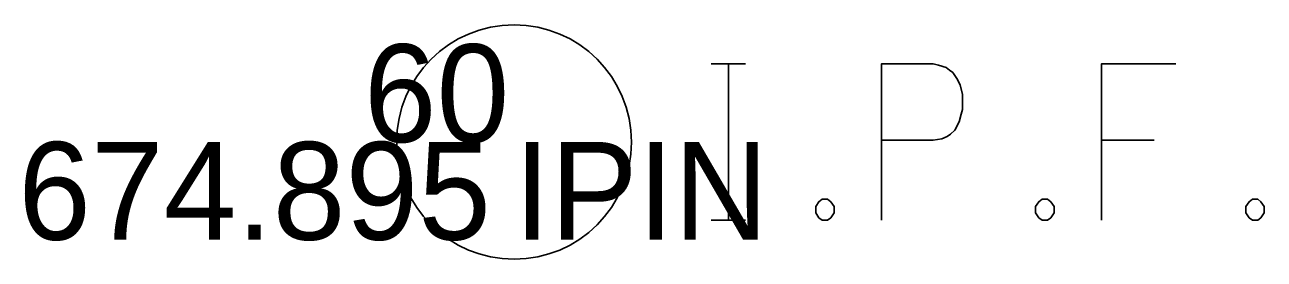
# Model space of a CAD drawing. Extents: x 2197382 to 2204062, y 634117 to 636522.
# Drawn here: x 2198210.64 to 2198223.31, y 636315.52 to 636317.92 of the extents above; entities that cross this region are included whole.
import ezdxf

# ---------------------------------------------------------------- set-up
doc = ezdxf.new("R2010")
doc.units = 0
for name, color, linetype in [('SH_Border', 7, 'Continuous'), ('SH_Cut_Line', 7, 'Continuous'), ('SH_Data', 7, 'Continuous'), ('SV_X_Mon_Cells_Found', 7, 'Continuous')]:
    doc.layers.add(name, color=color, linetype=linetype)

msp = doc.modelspace()

# ---------------------------------------------------------------- linework, layer by layer
at = {"layer": 'SV_X_Mon_Cells_Found'}
for points in [[(2198217.654, 636317.52), (2198218.007, 636317.52)], [(2198217.831, 636315.92), (2198217.831, 636317.52)], [(2198219.396, 636315.92), (2198219.396, 636317.52), (2198219.925, 636317.52), (2198219.98, 636317.508), (2198220.057, 636317.482), (2198220.091, 636317.457), (2198220.124, 636317.432), (2198220.168, 636317.369), (2198220.201, 636317.306), (2198220.223, 636317.205), (2198220.223, 636317.054), (2198220.212, 636317.004), (2198220.19, 636316.928), (2198220.146, 636316.84), (2198220.101, 636316.802), (2198220.068, 636316.777), (2198220.013, 636316.752), (2198219.925, 636316.739), (2198219.396, 636316.739)], [(2198222.405, 636317.52), (2198221.645, 636317.52), (2198221.645, 636315.92)], [(2198221.645, 636316.739), (2198222.185, 636316.739)], [(2198218.79, 636316.135), (2198218.845, 636316.135), (2198218.878, 636316.109), (2198218.911, 636316.059), (2198218.911, 636315.996), (2198218.878, 636315.945), (2198218.845, 636315.92), (2198218.79, 636315.92), (2198218.757, 636315.945), (2198218.724, 636315.996), (2198218.724, 636316.059), (2198218.757, 636316.109), (2198218.79, 636316.135)], [(2198221.039, 636316.135), (2198221.094, 636316.135), (2198221.127, 636316.109), (2198221.16, 636316.059), (2198221.16, 636315.996), (2198221.127, 636315.945), (2198221.094, 636315.92), (2198221.039, 636315.92), (2198221.005, 636315.945), (2198220.972, 636315.996), (2198220.972, 636316.059), (2198221.005, 636316.109), (2198221.039, 636316.135)], [(2198223.188, 636316.135), (2198223.243, 636316.135), (2198223.276, 636316.109), (2198223.309, 636316.059), (2198223.309, 636315.996), (2198223.276, 636315.945), (2198223.243, 636315.92), (2198223.188, 636315.92), (2198223.155, 636315.945), (2198223.122, 636315.996), (2198223.122, 636316.059), (2198223.155, 636316.109), (2198223.188, 636316.135)], [(2198217.654, 636315.92), (2198218.007, 636315.92)]]:
    msp.add_lwpolyline(points, dxfattribs=at)
msp.add_circle((2198215.64, 636316.72), 1.2, dxfattribs=at)

# ---------------------------------------------------------------- texts
at = {"layer": 'SH_Border'}
msp.add_text('IPIN', height=1, dxfattribs=at).set_placement((2198215.64, 636315.72))
at = {"layer": 'SH_Cut_Line'}
msp.add_text('60', height=1, dxfattribs=at).set_placement((2198214.104, 636316.72))
at = {"layer": 'SH_Data'}
msp.add_text('674.895', height=1, dxfattribs=at).set_placement((2198210.57, 636315.72))

doc.saveas('drawing.dxf')
